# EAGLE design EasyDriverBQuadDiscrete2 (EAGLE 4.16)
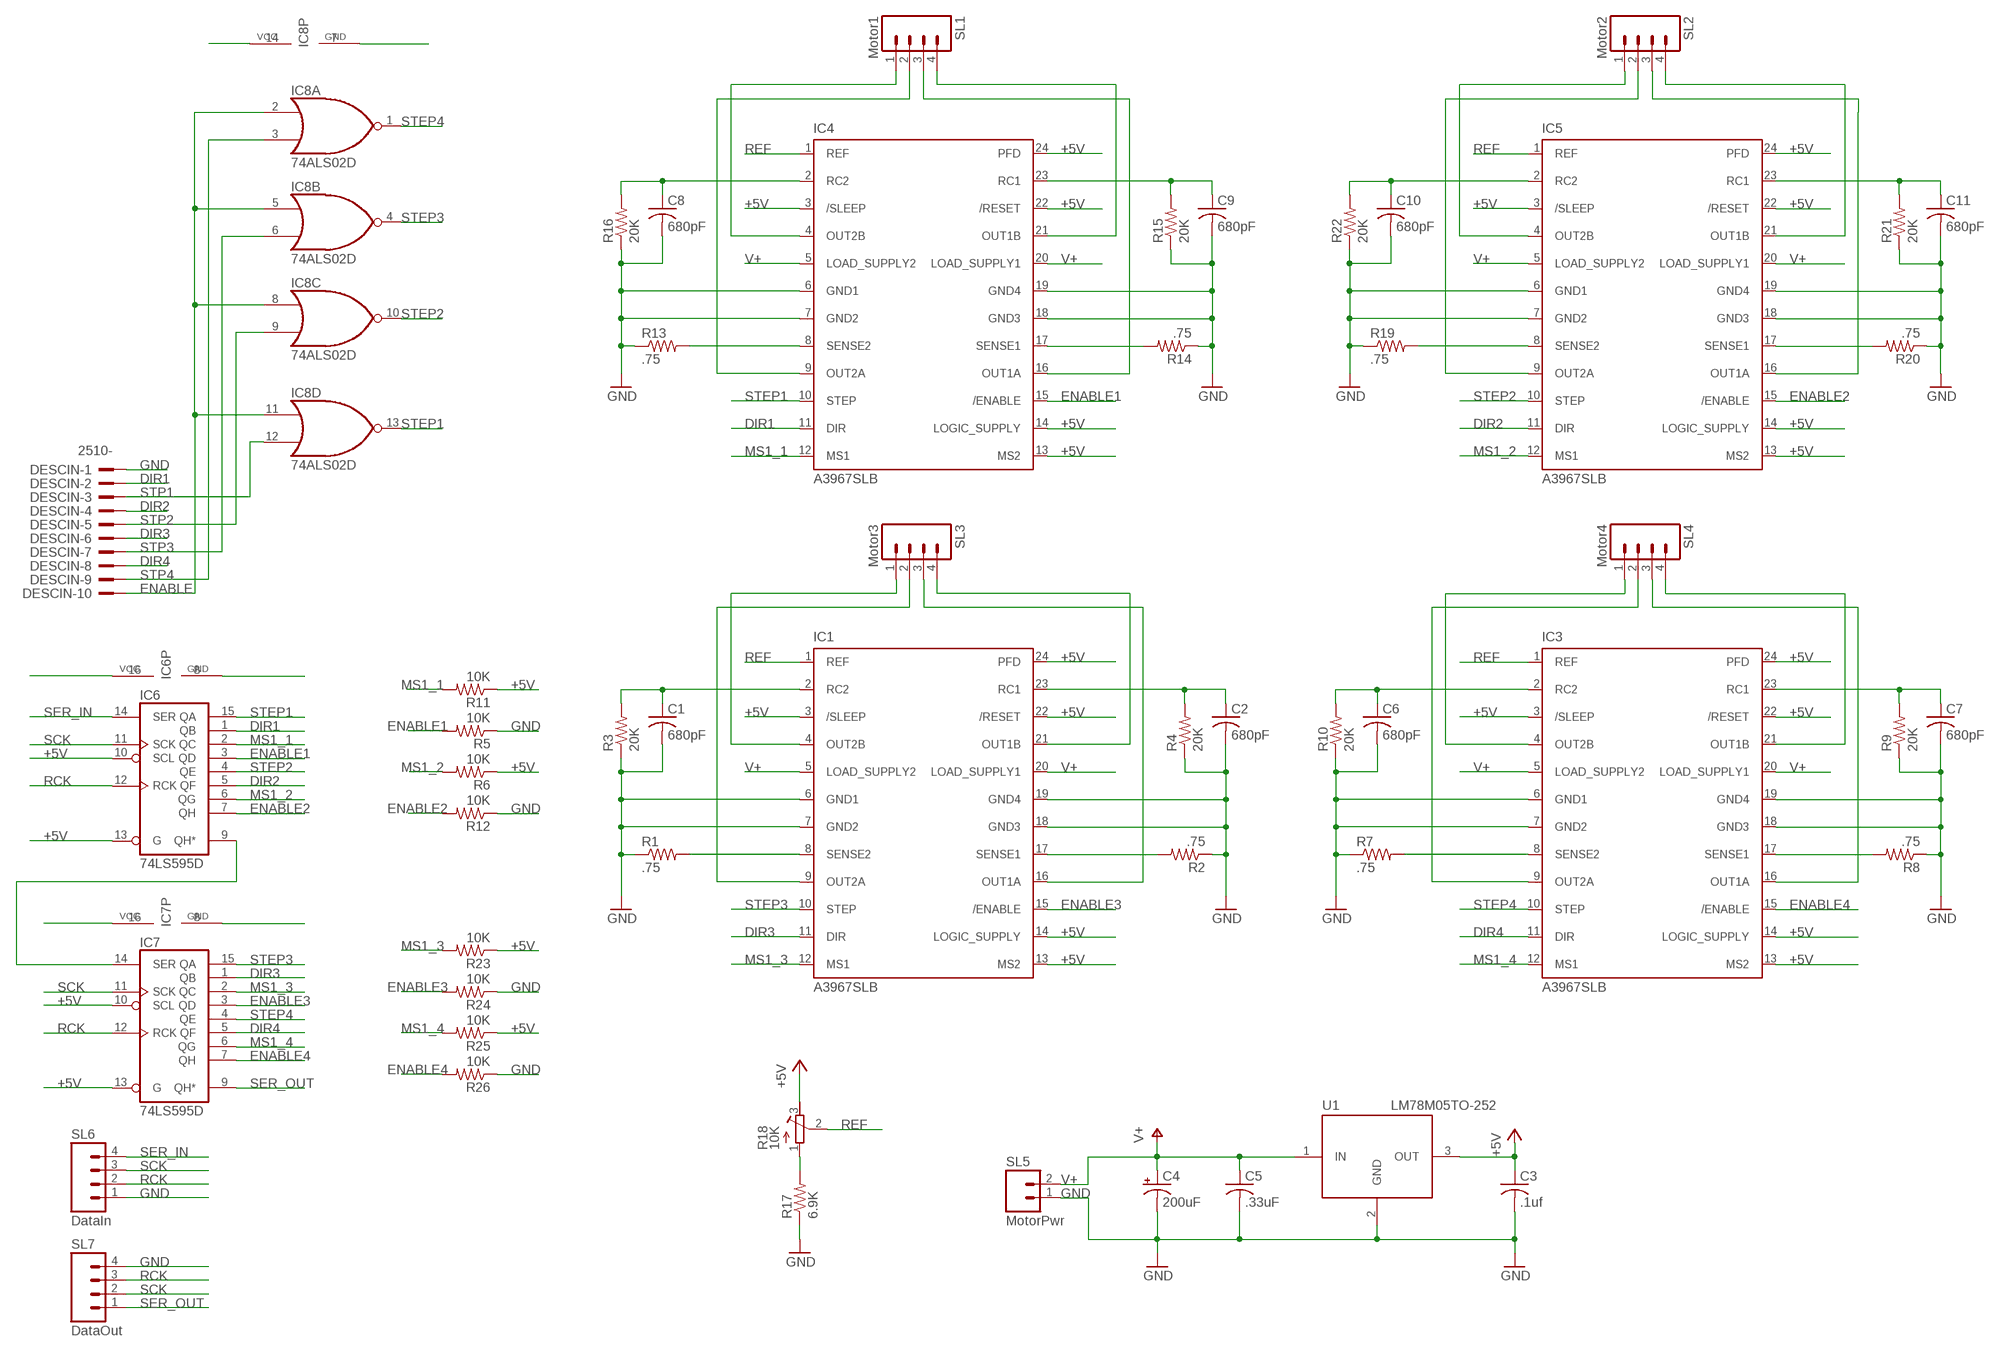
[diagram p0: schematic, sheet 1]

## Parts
C1  680pF  C-USC0603  [C0603]
C2  680pF  C-USC0603  [C0603]
C3  .1uf  C-USC0603  [C0603]
C4  200uF  CPOL-USG  [PANASONIC_G]
C5  .33uF  C-USC0603  [C0603]
C6  680pF  C-USC0603  [C0603]
C7  680pF  C-USC0603  [C0603]
C8  680pF  C-USC0603  [C0603]
C9  680pF  C-USC0603  [C0603]
C10  680pF  C-USC0603  [C0603]
C11  680pF  C-USC0603  [C0603]
DESCIN  2510-  [PAK100/2500-10]
IC1  A3967SLB  [SO24W]
IC3  A3967SLB  [SO24W]
IC4  A3967SLB  [SO24W]
IC5  A3967SLB  [SO24W]
IC6  74LS595D  [SO16]
IC7  74LS595D  [SO16]
IC8  74ALS02D  [SO14]
R1  .75  R-US_R0805  [R0805]
R2  .75  R-US_R0805  [R0805]
R3  20K  R-US_R0603  [R0603]
R4  20K  R-US_R0603  [R0603]
R5  10K  R-US_R0603  [R0603]
R6  10K  R-US_R0603  [R0603]
R7  .75  R-US_R0805  [R0805]
R8  .75  R-US_R0805  [R0805]
R9  20K  R-US_R0603  [R0603]
R10  20K  R-US_R0603  [R0603]
R11  10K  R-US_R0603  [R0603]
R12  10K  R-US_R0603  [R0603]
R13  .75  R-US_R0805  [R0805]
R14  .75  R-US_R0805  [R0805]
R15  20K  R-US_R0603  [R0603]
R16  20K  R-US_R0603  [R0603]
R17  6.9K  R-US_R0603  [R0603]
R18  10K  R-TRIMM3103  [RTRIM3103]
R19  .75  R-US_R0805  [R0805]
R20  .75  R-US_R0805  [R0805]
R21  20K  R-US_R0603  [R0603]
R22  20K  R-US_R0603  [R0603]
R23  10K  R-US_R0603  [R0603]
R24  10K  R-US_R0603  [R0603]
R25  10K  R-US_R0603  [R0603]
R26  10K  R-US_R0603  [R0603]
SL1  Motor1  M04POLAR  [MOLEX-1X4]
SL2  Motor2  M04POLAR  [MOLEX-1X4]
SL3  Motor3  M04POLAR  [MOLEX-1X4]
SL4  Motor4  M04POLAR  [MOLEX-1X4]
SL5  MotorPwr  M02SCREW  [SCREWTERMINAL-3.5MM-2]
SL6  DataIn  M04POLAR  [MOLEX-1X4]
SL7  DataOut  M04POLAR  [MOLEX-1X4]
U1  LM78M05TO-252  [TOO-252]

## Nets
+5V: C3.1 IC1.3(/SLEEP) IC1.13(MS2) IC1.14(LOGIC_SUPPLY) IC1.22(/RESET) IC1.24(PFD) IC3.3(/SLEEP) IC3.13(MS2) IC3.14(LOGIC_SUPPLY) IC3.22(/RESET) IC3.24(PFD) IC4.3(/SLEEP) IC4.13(MS2) IC4.14(LOGIC_SUPPLY) IC4.22(/RESET) IC4.24(PFD) IC5.3(/SLEEP) IC5.13(MS2) IC5.14(LOGIC_SUPPLY) IC5.22(/RESET) IC5.24(PFD) IC6.10(SCL) IC6.13(G) IC6.16(VCC) IC7.10(SCL) IC7.13(G) IC7.16(VCC) IC8.14(P:VCC) R6.1 R11.1 R18.3(A) R23.1 R25.1 U1.3(OUT)
DIR1: DESCIN.2 IC4.11(DIR) IC6.1(QB)
DIR2: DESCIN.4 IC5.11(DIR) IC6.5(QF)
DIR3: DESCIN.6 IC1.11(DIR) IC7.1(QB)
DIR4: DESCIN.8 IC3.11(DIR) IC7.5(QF)
ENABLE: DESCIN.10 IC8.2(A:I0) IC8.5(B:I0) IC8.8(C:I0) IC8.11(D:I0)
ENABLE1: IC4.15(/ENABLE) IC6.3(QD) R5.2
ENABLE2: IC5.15(/ENABLE) IC6.7(QH) R12.2
ENABLE3: IC1.15(/ENABLE) IC7.3(QD) R24.2
ENABLE4: IC3.15(/ENABLE) IC7.7(QH) R26.2
GND: C1.2 C2.2 C3.2 C4.- C5.2 C6.2 C7.2 C8.2 C9.2 C10.2 C11.2 DESCIN.1 IC1.6(GND1) IC1.7(GND2) IC1.18(GND3) IC1.19(GND4) IC3.6(GND1) IC3.7(GND2) IC3.18(GND3) IC3.19(GND4) IC4.6(GND1) IC4.7(GND2) IC4.18(GND3) IC4.19(GND4) IC5.6(GND1) IC5.7(GND2) IC5.18(GND3) IC5.19(GND4) IC6.8(GND) IC7.8(GND) IC8.7(P:GND) R1.1 R2.1 R3.1 R4.1 R5.1 R7.1 R8.1 R9.1 R10.1 R12.1 R13.1 R14.1 R15.1 R16.1 R17.1 R19.1 R20.1 R21.1 R22.1 R24.1 R26.1 SL5.1 SL6.1 SL7.4 U1.2(GND)
MS1_1: IC4.12(MS1) IC6.2(QC) R11.2
MS1_2: IC5.12(MS1) IC6.6(QG) R6.2
MS1_3: IC1.12(MS1) IC7.2(QC) R23.2
MS1_4: IC3.12(MS1) IC7.6(QG) R25.2
N$1: IC1.8(SENSE2) R1.2
N$2: IC1.21(OUT1B) SL3.4
N$3: IC1.17(SENSE1) R2.2
N$4: IC4.4(OUT2B) SL1.1
N$5: C1.1 IC1.2(RC2) R3.2
N$6: IC5.4(OUT2B) SL2.1
N$7: C2.1 IC1.23(RC1) R4.2
N$9: IC1.9(OUT2A) SL3.2
N$11: IC3.16(OUT1A) SL4.3
N$12: IC3.21(OUT1B) SL4.4
N$13: IC3.4(OUT2B) SL4.1
N$14: IC3.9(OUT2A) SL4.2
N$15: IC1.4(OUT2B) SL3.1
N$16: IC4.16(OUT1A) SL1.3
N$17: IC5.16(OUT1A) SL2.3
N$19: IC3.8(SENSE2) R7.2
N$20: IC3.17(SENSE1) R8.2
N$21: C6.1 IC3.2(RC2) R10.2
N$22: C7.1 IC3.23(RC1) R9.2
N$23: IC1.16(OUT1A) SL3.3
N$26: IC4.9(OUT2A) SL1.2
N$28: IC4.21(OUT1B) SL1.4
N$31: IC4.8(SENSE2) R13.2
N$32: IC4.17(SENSE1) R14.2
N$33: C8.1 IC4.2(RC2) R16.2
N$34: C9.1 IC4.23(RC1) R15.2
N$35: R17.2 R18.1(E)
N$38: IC5.9(OUT2A) SL2.2
N$40: IC5.21(OUT1B) SL2.4
N$43: IC5.8(SENSE2) R19.2
N$44: IC5.17(SENSE1) R20.2
N$45: C10.1 IC5.2(RC2) R22.2
N$46: C11.1 IC5.23(RC1) R21.2
N$54: IC6.9(QH*) IC7.14(SER)
RCK: IC6.12(RCK) IC7.12(RCK) SL6.2 SL7.3
REF: IC1.1(REF) IC3.1(REF) IC4.1(REF) IC5.1(REF) R18.2(S)
SCK: IC6.11(SCK) IC7.11(SCK) SL6.3 SL7.2
SER_IN: IC6.14(SER) SL6.4
SER_OUT: IC7.9(QH*) SL7.1
STEP1: IC4.10(STEP) IC6.15(QA) IC8.13(D:O)
STEP2: IC5.10(STEP) IC6.4(QE) IC8.10(C:O)
STEP3: IC1.10(STEP) IC7.15(QA) IC8.4(B:O)
STEP4: IC3.10(STEP) IC7.4(QE) IC8.1(A:O)
STP1: DESCIN.3 IC8.12(D:I1)
STP2: DESCIN.5 IC8.9(C:I1)
STP3: DESCIN.7 IC8.6(B:I1)
STP4: DESCIN.9 IC8.3(A:I1)
V+: C4.+ C5.1 IC1.5(LOAD_SUPPLY2) IC1.20(LOAD_SUPPLY1) IC3.5(LOAD_SUPPLY2) IC3.20(LOAD_SUPPLY1) IC4.5(LOAD_SUPPLY2) IC4.20(LOAD_SUPPLY1) IC5.5(LOAD_SUPPLY2) IC5.20(LOAD_SUPPLY1) SL5.2 U1.1(IN)

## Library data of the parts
C1-C3 C5-C11 = rcl:C-US: CAPACITOR, American symbol
C4 = rcl:CPOL-US: POLARIZED CAPACITOR, American symbol
DESCIN = con-3m:2510-: 3M (TM) Pak 100 4-Wall Header Source: 3M
IC1 IC3-IC5 = Allegro:A3967SLB: ANALOG DEVICES
IC6 IC7 = SparkFunEagle-6-6-07:74*595: 8-bit SHIFT REGISTER, output latch
IC8 = 74xx-us:74*02: Quad 2-input NOR gate
R1-R17 R19-R26 = rcl:R-US_: RESISTOR, American symbol
R18 = rcl:R-TRIMM: Trimm resistor
SL1-SL4 SL6 SL7 = SparkFunEagle-6-6-07:M04: Header 4 Standard 4-pin 0.1" header. Use with straight break away headers (SKU : PRT-00116), right angle break away headers (PRT-00553), swiss pins (PRT-00743), machine pins (PRT-00117), and female headers (PRT-00115). Molex polarized connector foot print use with SKU : PRT-08231 with associated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
SL5 = SparkFunEagle-6-6-07:M02: Header 2
U1 = BriansLibrary:LM78M05

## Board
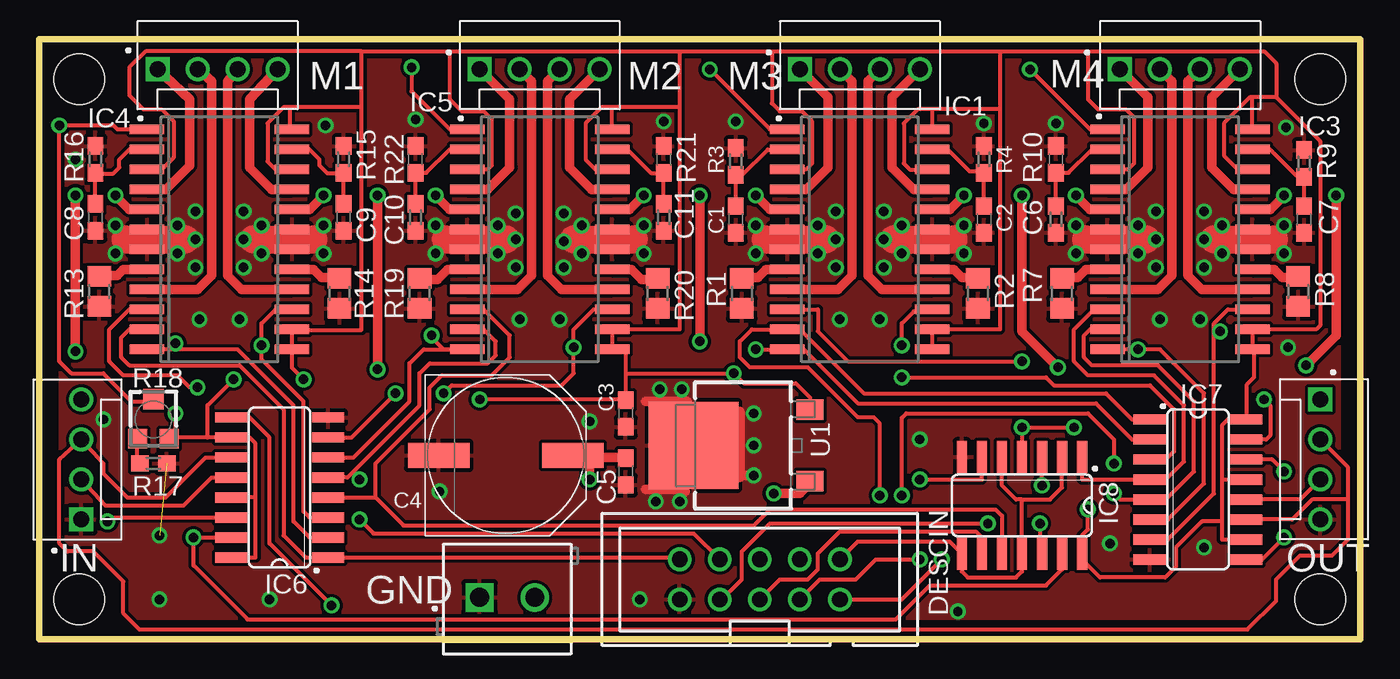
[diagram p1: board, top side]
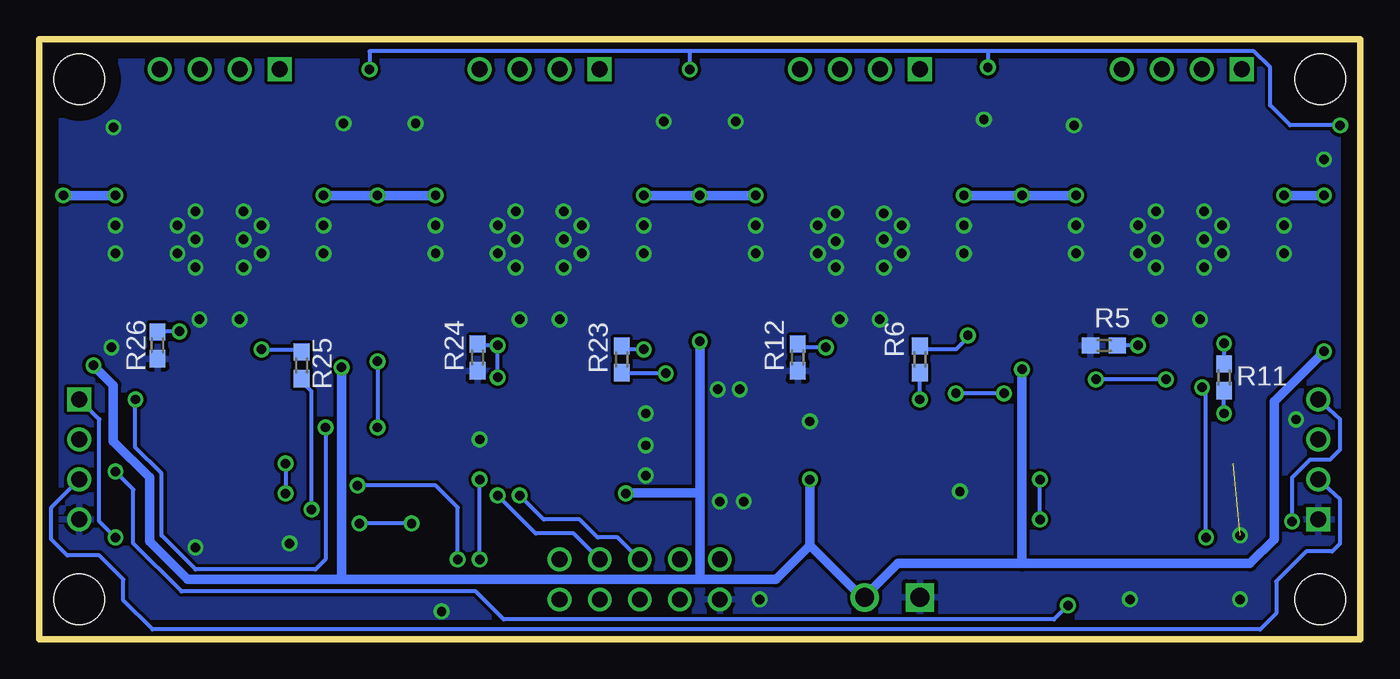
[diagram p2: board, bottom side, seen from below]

Size 83.82 x 38.1 mm. Coordinates in mm from the lower left corner, seen from the top.
Outline: 0,38.1 0,0 83.82,0 83.82,38.1 0,38.1
Copper layers (1*16): Top 0.035mm / dielectric 1.5mm / Bottom 0.035mm
Design rules "default": minimum track width 8mil, minimum drill 20mil, track to track 8mil, track to pad 8mil, pad to pad 8mil, via to via 8mil, smd to smd 8mil, copper to edge 40mil, drill to drill 8mil, minimum pad ring 10mil, minimum via ring 8mil, stop-mask expansion 4mil, vias tented up to drill 0mil, thermal gap 10mil
Holes 3.2 mm at 2.54,35.56 81.28,35.56 2.54,2.54 81.28,2.54

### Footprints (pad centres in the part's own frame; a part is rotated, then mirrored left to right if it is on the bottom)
C0603 = smd 1.1 x 1: 1 -0.85,0; 2 0.85,0
PANASONIC_G = smd 3.9 x 1.6: + 4.25,0; - -4.25,0
PAK100/2500-10 = drill 1 pad 1.422 round: 1 -5.08,-1.27; 2 -5.08,1.27; 3 -2.54,-1.27; 4 -2.54,1.27; 5 0,-1.27; 6 0,1.27; 7 2.54,-1.27; 8 2.54,1.27; 9 5.08,-1.27; 10 5.08,1.27
SO24W = smd 0.6 x 2.2: 1 -6.985,-4.6; 2 -5.715,-4.6; 3 -4.445,-4.6; 4 -3.175,-4.6; 5 -1.905,-4.6; 6 -0.635,-4.6; 7 0.635,-4.6; 8 1.905,-4.6; 9 3.175,-4.6; 10 4.445,-4.6; 11 5.715,-4.6; 12 6.985,-4.6; 13 6.985,4.6; 14 5.715,4.6; 15 4.445,4.6; 16 3.175,4.6; 17 1.905,4.6; 18 0.635,4.6; 19 -0.635,4.6; 20 -1.905,4.6; 21 -3.175,4.6; 22 -4.445,4.6; 23 -5.715,4.6; 24 -6.985,4.6
SO16 = smd 0.66 x 2.032: 1 -4.445,-3.073; 2 -3.175,-3.073; 3 -1.905,-3.073; 4 -0.635,-3.073; 5 0.635,-3.073; 6 1.905,-3.073; 7 3.175,-3.073; 8 4.445,-3.073; 9 4.445,3.073; 10 3.175,3.073; 11 1.905,3.073; 12 0.635,3.073; 13 -0.635,3.073; 14 -1.905,3.073; 15 -3.175,3.073; 16 -4.445,3.073
SO14 = smd 0.66 x 2.032: 1 -3.81,-3.073; 2 -2.54,-3.073; 3 -1.27,-3.073; 4 0,-3.073; 5 1.27,-3.073; 6 2.54,-3.073; 7 3.81,-3.073; 8 3.81,3.073; 9 2.54,3.073; 10 1.27,3.073; 11 0,3.073; 12 -1.27,3.073; 13 -2.54,3.073; 14 -3.81,3.073
R0805 = smd 1.3 x 1.5: 1 -0.95,0; 2 0.95,0
R0603 = smd 1.1 x 1: 1 -0.85,0; 2 0.85,0
RTRIM3103 = smd 1.2 x 1.25: 1 -1,-1.225; 3 1,-1.225 | smd 1.3 x 1.3: 2 0,1.3
MOLEX-1X4 = drill 1.016 square: 1 3.81,-2.54 | drill 1.016 round: 2 1.27,-2.54; 3 -1.27,-2.54; 4 -3.81,-2.54
SCREWTERMINAL-3.5MM-2 = drill 1.2 square: 1 -1.905,0 | drill 1.2 round: 2 1.595,0
TOO-252 = smd 1.3 x 1.7: 1 -2.28,-3.7; 3 2.28,-3.7 | smd 5.5 x 5.7: 2 0,3.7

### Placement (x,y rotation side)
C1  44.2,26.67 270 top
C2  59.94,26.67 270 top
C3  37.21,14.35 270 top
C4  29.59,11.68 0 top
C5  37.21,10.67 270 top
C6  64.52,30.48 90 top
C7  80.26,26.67 270 top
C8  3.56,26.8 270 top
C9  19.3,26.8 270 top
C10  23.88,30.48 90 top
C11  39.62,30.48 90 top
DESCIN  45.72,3.81 0 top
IC1  52.07,25.4 270 top
IC3  72.39,25.4 270 top
IC4  11.43,25.4 270 top
IC5  31.75,25.4 270 top
IC6  15.24,9.65 90 top
IC7  73.53,9.53 270 top
IC8  62.36,8.51 180 top
R1  44.58,21.97 90 top
R2  59.56,21.97 90 top
R3  44.2,30.35 270 top
R4  59.94,30.48 270 top
R5  16.26,18.67 0 bottom
R6  27.94,17.78 90 bottom
R7  64.9,21.97 90 top
R8  79.88,22.1 90 top
R9  80.26,30.23 270 top
R10  64.52,26.67 90 top
R11  8.64,16.64 90 bottom
R12  35.69,17.91 90 bottom
R13  3.81,22.1 90 top
R14  19.05,21.97 90 top
R15  19.3,30.48 270 top
R16  3.56,30.48 270 top
R17  7.24,11.18 180 top
R18  7.24,13.97 0 top
R19  24.13,21.97 90 top
R20  39.24,21.97 90 top
R21  39.62,26.8 90 top
R22  23.88,26.8 90 top
R23  46.86,17.78 90 bottom
R24  56.01,17.91 90 bottom
R25  67.18,17.4 90 bottom
R26  76.33,18.67 90 bottom
SL1  11.3,33.66 180 top
SL2  31.75,33.66 180 top
SL3  52.07,33.66 180 top
SL4  72.39,33.66 180 top
SL5  29.84,2.67 0 top
SL6  5.21,11.43 270 top
SL7  78.74,11.43 90 top
U1  45.21,12.32 90 top

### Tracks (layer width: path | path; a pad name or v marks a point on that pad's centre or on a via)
+5V  (via drill 0.6)
  Top 0.254: 16.89,32.38 IC4.24 15.88,32.38 15.88,33.78 | 16,19.68 15.88,19.56 | 12.19,12.83 13.34,12.83 13.72,12.45 13.72,9.02 | 13.72,9.02 IC6.13 | IC6.16 13.72,5.21 13.72,9.02 | 77.09,19.68 77.12,19.71 77.12,19.66 | 56.67,19.59 56.64,19.56 | IC4.22 14.99,29.84 14.48,30.35 14.48,32.77 15.49,33.78 15.88,33.78 | 5.97,29.84 IC4.3 7.75,29.84 8.51,30.61 8.51,32.89 7.75,33.66 6.6,33.66 5.71,34.54 5.71,36.32 6.73,37.34 20.45,37.34 | IC5.22 35.31,29.84 34.67,30.48 34.67,32.77 35.69,33.78 36.32,33.78 | 40.64,33.78 36.32,33.78 | 40.64,37.34 40.64,33.78 | 40.64,33.78 40.64,19.68 IC5.14 36.35,18.44 36.32,18.41 IC5.13 37.21,18.41 37.21,16.89 | IC5.3 28.45,29.84 28.7,30.1 28.7,33.02 28.19,33.53 26.8,33.53 26.04,34.29 26.04,37.34 | IC1.3 48.64,29.84 49.02,30.23 49.02,32.89 48.39,33.53 46.99,33.53 46.48,34.04 46.48,37.34 | IC1.22 55.24,29.84 54.86,30.23 54.86,32.77 55.75,33.66 56.64,33.66 | 60.96,33.66 56.64,33.66 | IC3.3 69.09,29.84 69.47,30.23 69.47,33.15 68.96,33.66 67.18,33.66 66.55,34.29 66.55,37.34 | IC3.22 76.07,29.84 75.18,30.73 75.18,32.77 76.83,34.42 76.96,34.42 | 78.49,34.42 81.28,31.62 81.28,19.94 81.03,19.68 77.09,19.68 | 78.49,34.42 76.96,34.42 | 20.45,33.78 15.88,33.78 | IC5.24 36.32,32.38 36.32,33.78 | 16,19.68 IC4.14 | 16.03,19.66 IC4.13 16.03,17.24 v16.76,16.51 | 16.03,19.66 16,19.68 | IC1.24 56.67,32.36 56.64,32.38 56.64,33.66 | 40.64,37.34 46.48,37.34 | 56.64,19.68 56.64,18.41 IC1.13 | IC3.13 77.09,18.41 | IC3.13 76.99,19.66 76.96,19.68 IC3.14 77.09,19.68 | 76.96,34.42 76.96,32.38 IC3.24 | 20.45,37.34 26.04,37.34 | IC7.10 75.06,6.35 75.06,7.49 | 75.06,10.16 75.06,7.49 | 75.06,10.16 IC7.13
  Top 0.254: 75.06,10.16 75.06,13.59 75.44,13.97 IC7.16 76.61,16.15 77.09,16.64 77.09,18.29 76.96,18.41 IC3.13 | 75.06,7.49 73.79,7.49 72.14,5.84 72.14,4.62 71.45,3.94 67.31,3.94 66.17,5.08 IC8.14 66.17,6.6 66.55,6.99 v66.55,8.26 | 20.45,33.78 20.45,37.34 | 26.04,37.34 40.64,37.34 | 46.48,37.34 60.96,37.34 | 60.96,37.34 66.55,37.34 | 66.55,37.34 77.72,37.34 78.49,36.58 78.49,34.42 | 60.96,37.34 60.96,33.66 | 60.96,33.66 60.96,19.68 56.64,19.68 | 56.64,19.68 IC1.14 | 10.67,12.83 8.26,12.83 8.26,12.76 R18.3 8.24,12.81 8.64,13.21 v8.64,14.35 | 12.19,12.83 IC6.10 | 12.19,12.83 10.67,12.83 | 37.21,15.24 v27.94,15.24 | 16.03,19.66 20.45,19.66 20.45,33.78 | v12.32,16.51 10.67,14.86 10.67,12.83 | 37.21,15.24 C3.1 | 37.21,16.89 v44.07,16.89 44.7,16.26 48.01,16.26 48.91,15.35 48.91,14.62 48.9,14.61 U1.3 | 37.21,16.89 37.21,15.24
  Top 0.406: IC5.14 36.32,19.68 | IC1.14 56.67,19.59
  Bottom 0.254: v27.94,15.24 R6.1 | v8.64,14.35 R11.1 | R23.1 46.86,16.89 v44.07,16.89 | R25.1 67.18,16.38 66.55,15.75 v66.55,8.26 | v12.32,16.51 v16.76,16.51
DIR1
  Top 0.254: 7.75,19.68 IC4.11 5.71,19.68 5.21,19.18 5.21,17.91 5.71,17.4 12.7,17.4 15.49,14.61 15.49,6.6 16.89,5.21 IC6.1 40.51,5.21 DESCIN.2
DIR2  (via drill 0.6)
  Top 0.254: 27.18,19.68 IC5.11 28.19,19.68 28.96,18.92 28.96,18.03 28.45,17.53 24.77,17.53 24.13,16.89 24.13,14.86 19.94,10.67 | IC6.5 19.56,10.29 19.94,10.67 | DESCIN.4 41.53,6.73 21.21,6.73 v20.32,7.62 | v20.32,10.16 20.32,10.29 19.94,10.67
  Bottom 0.254: v20.32,7.62 v20.32,10.16
DIR3  (via drill 0.6)
  Top 0.254: IC7.1 69.34,13.97 67.69,15.62 52.32,15.62 48.26,19.68 IC1.11 45.21,19.68 44.45,18.92 44.45,17.91 45.09,17.27 48.77,17.27 51.94,14.1 52.96,14.1 53.34,13.72 v53.34,9.14
  Bottom 0.254: v53.34,9.14 51.82,7.62 49.53,7.62 48.39,6.48 47.12,6.48 DESCIN.6
DIR4  (via drill 0.6)
  Top 0.254: IC3.11 66.67,19.68 66.29,19.3 66.29,17.91 66.8,17.4 70.99,17.4 73.28,15.11 73.28,10.67 71.5,8.89 IC7.5 68.58,8.89 v68.2,9.27 | v68.2,11.18 68.2,12.7 66.55,14.35 55.02,14.35 54.74,14.07 v54.74,9.14
  Bottom 0.254: v68.2,11.18 v68.2,9.27 | DESCIN.8 49.91,6.73 52.32,6.73 v54.74,9.14
ENABLE
  Top 0.254: IC8.2 64.9,9.65 64.14,8.89 62.36,8.89 | 62.36,8.89 61.98,8.89 61.09,9.78 IC8.5 | IC8.11 62.36,6.1 | IC8.11 62.36,8.89 | IC8.11 62.36,4.32 61.98,3.94 58.93,3.94 58.55,4.32 IC8.8 57.76,6.22 51.94,6.22 DESCIN.10
ENABLE1  (via drill 0.6)
  Top 0.254: IC4.15 14.99,20.95 14.1,20.07 14.1,19.05 | 14.1,19.05 14.1,18.92 | IC6.3 17.14,7.75 16.76,8.13 16.76,15.11 14.1,17.78 v14.1,18.67 14.1,19.05
  Bottom 0.254: v14.1,18.67 R5.2
ENABLE2  (via drill 0.6)
  Top 0.254: IC5.15 36.32,20.95 36.2,20.83 36.07,20.95 35.18,20.95 33.91,19.68 v33.91,18.54 33.91,16.89 33.15,16.13 26.16,16.13 v25.65,15.62 | IC6.7 19.81,12.83 v22.61,15.62
  Bottom 0.254: v33.91,18.54 35.69,18.54 R12.2 | v22.61,15.62 v25.65,15.62
ENABLE3  (via drill 0.6)
  Top 0.254: 56.64,20.83 56.67,20.86 IC1.15 | 56.64,20.83 57.4,20.83 | 56.64,20.83 55.5,20.83 54.74,20.07 v54.74,18.67 | IC7.3 71.5,11.43 72.01,11.94 72.01,14.61 70.48,16.13 64.39,16.13 63.88,16.64 v54.74,16.64
  Bottom 0.254: R24.2 56.01,18.67 v54.74,18.67 v54.74,16.64
ENABLE4  (via drill 0.6)
  Top 0.254: IC7.7 71.63,6.35 74.55,9.27 74.55,19.56 | IC3.15 75.44,20.95 74.55,20.07 74.55,19.56 | 74.55,19.56 v74.93,19.56
  Bottom 0.254: R26.2 76.33,19.56 v74.93,19.56
GND  (via drill 0.6)  (1 unrouted)
  Top 0.254: 6.86,26.04 6.77,25.95 | IC4.19 16.13,26.04 | IC6.8 17.91,14.1
  Top 0.406: IC4.6 6.86,26.04 | IC4.7 6.86,24.77 | IC4.18 16,24.77
  Top 0.61: 16.13,26.04 16.22,25.95 | 38.48,15.11 41.02,15.11 | 41.02,15.11 41.15,15.11 | 38.48,9.53 40.89,9.53 41.02,9.4 40.64,9.02 v40.64,8.76 | 44.45,14.48 44.45,10.29 44.58,10.41 v45.34,10.41 | v40.77,15.88 40.77,15.37 41.02,15.11
  Top 1.778: 13.59,25.4 17.4,25.4 | 5.46,25.4 9.27,25.4 | 33.91,25.4 37.72,25.4 | 25.78,25.4 29.59,25.4 | 46.1,25.4 49.91,25.4 | 54.23,25.4 58.04,25.4 | 74.55,25.4 78.36,25.4 | 66.42,25.4 70.23,25.4
  other vias: 8.76,26.29 8.76,24.51 14.1,24.51 14.1,26.29 2.29,30.48 18.16,32.64 23.88,33.02 18.03,24.51 4.83,26.29 4.83,24.51 9.91,27.18 9.91,23.62 18.03,26.29 12.95,27.18 12.95,23.62 9.91,25.4 12.95,25.4 38.35,26.29 38.35,24.51 34.42,26.29 34.42,24.51 33.27,25.27 33.27,27.05 33.27,23.62 30.23,27.05 29.08,26.29 30.23,25.4 29.08,24.51 30.23,23.62 25.15,26.29 25.15,24.51 58.67,26.29 58.67,24.51 54.74,26.29 54.74,24.51 53.59,25.4 53.59,27.18 53.59,23.62 50.55,25.4 50.55,27.18 50.55,23.62 49.4,26.29 49.4,24.51 45.47,26.29 45.47,24.51 78.99,24.51 78.99,26.29 75.06,26.29 75.06,24.51 73.91,25.4 73.91,27.18 73.91,23.62 70.87,27.18 70.87,25.4 70.87,23.62 69.72,24.51 69.72,26.29 65.79,26.29 65.79,24.51 44.2,32.89 64.52,32.77 39.62,32.89 59.94,32.77 79.12,32.51 73.66,20.32 71.12,20.32 53.34,20.32 50.8,20.32 33.02,20.32 30.48,20.32 12.7,20.32 10.16,20.32 38.1,2.54 4.06,13.97 34.92,13.84 7.62,2.54 73.91,5.84 58.29,1.78 25.4,9.4 14.61,2.54 7.62,6.6 55.88,12.7 67.94,6.1 79.25,18.54 45.34,14.35 45.34,12.32 39.12,8.76 39.37,15.88
  pour Bottom: 0,38.1 0,0 83.82,0 83.82,38.1
  pour Top: 0,38.1 0,0 83.82,0 83.82,38.1
MS1_1  (via drill 0.6)
  Top 0.254: IC6.2 17.14,6.48 16.13,7.49 16.13,14.86 12.57,18.41 8.64,18.41 | 8.64,18.41 IC4.12 | 8.64,18.41 v8.64,18.8
  Bottom 0.254: v8.64,18.8 R11.2
MS1_2  (via drill 0.6)
  Top 0.254: v24.89,19.3 24.89,19.18 25.65,18.41 IC5.12 24.38,18.41 23.5,17.53 23.5,15.11 19.94,11.56 IC6.6
  Bottom 0.254: R6.2 27.94,18.54 28.07,18.41 25.65,18.41 24.89,19.18 v24.89,19.3
MS1_3  (via drill 0.6)
  Top 0.254: IC7.2 69.34,12.7 67.06,14.99 51.94,14.99 48.51,18.41 47.5,18.41 | 47.5,18.41 47.62,18.54 | 47.5,18.41 IC1.12 v45.47,18.41
  Bottom 0.254: R23.2 46.86,18.67 46.61,18.41 v45.47,18.41
MS1_4  (via drill 0.6)
  Top 0.254: 70.46,7.64 70.36,7.75 | IC7.6 70.46,7.64 | 70.46,7.64 70.48,7.62 71.63,7.62 73.91,9.91 73.91,15.62 71.12,18.41 v69.72,18.41 IC3.12
  Bottom 0.254: R25.2 67.18,18.29 67.31,18.41 v69.72,18.41
N$1
  Top 0.61: IC1.8 46.1,23.5 45.59,22.99 44.58,22.99 R1.2
N$2
  Top 0.61: SL3.4 54.1,34.42 54.1,29.97 55.5,28.57 IC1.21
N$3
  Top 0.61: IC1.17 58.04,23.5 58.55,22.99 59.56,22.99 R2.2
N$4
  Top 0.61: IC4.4 8,28.57 9.53,30.1 9.53,34.29 SL1.1
N$5
  Top 0.254: C1.1 R3.2 44.62,29.5 46.23,31.11 47.37,31.11
  Top 0.406: 47.37,31.11 IC1.2
N$6
  Top 0.61: IC5.4 28.45,28.57 29.84,29.97 29.84,34.29 SL2.1
N$7
  Top 0.254: IC1.23 57.66,31.11 59.05,29.72 59.82,29.72 | C2.1 59.94,29.59 R4.2
  Top 0.406: 59.94,29.59 59.91,29.63 | 59.91,29.63 R4.2 | 59.91,29.63 59.82,29.72
N$9
  Top 0.406: IC1.9 47.37,22.23
  Top 0.61: SL3.2 51.56,35.43 51.56,23.11 50.67,22.23 IC1.9
N$11
  Top 0.61: IC3.16 73.79,22.23 72.9,23.11 72.9,35.43 SL4.3
N$12
  Top 0.61: IC3.21 75.82,28.57 74.42,29.97 74.42,34.42 SL4.4
N$13
  Top 0.61: IC3.4 68.96,28.57 70.36,29.97 70.36,34.42 SL4.1
N$14
  Top 0.61: IC3.9 70.99,22.23 71.88,23.11 71.88,35.43 SL4.2
N$15
  Top 0.61: IC1.4 48.64,28.57 50.04,29.97 50.04,34.42 SL3.1
N$16
  Top 0.61: IC4.16 12.83,22.23 11.94,23.11 11.94,35.43 SL1.3
N$17
  Top 0.61: IC5.16 33.15,22.23 32.26,23.11 32.26,35.43 SL2.3
N$19
  Top 0.406: 67.82,23.5 IC3.8
  Top 0.61: R7.2 64.9,22.99 65.91,22.99 66.42,23.5 67.82,23.5
N$20
  Top 0.61: R8.2 79.88,22.99 78.87,22.99 78.36,23.5 IC3.17
N$21
  Top 0.254: R10.2 64.52,29.59 | C6.1 65.32,29.63 66.8,31.11 IC3.2
  Top 0.406: 64.52,29.59 C6.1
N$22
  Top 0.254: IC3.23 78.11,31.11 79.76,29.46 80.14,29.46 80.26,29.34 R9.2 C7.1 80.26,27.43
N$23
  Top 0.61: IC1.16 53.47,22.23 52.58,23.11 52.58,35.43 SL3.3
N$26
  Top 0.61: IC4.9 10.03,22.23 10.92,23.11 10.92,35.43 SL1.2
N$28
  Top 0.61: IC4.21 14.73,28.57 13.34,29.97 13.34,34.29 SL1.4
N$31
  Top 0.61: 6.86,23.5 IC4.8 5.33,23.5 4.95,23.11 3.81,23.11 R13.2 3.81,22.99
N$32
  Top 0.61: IC4.17 17.4,23.5 17.91,22.99 18.92,22.99 | 18.92,22.99 19.05,22.99 | 18.92,22.99 18.92,22.86 18.98,22.92 R14.2
N$33
  Top 0.254: IC4.2 5.71,31.11 5.08,30.48 5.08,29.97 4.7,29.59 3.56,29.59 | C8.1 3.56,29.59 | 3.56,29.59 R16.2
  Top 0.406: IC4.2 6.86,31.11
N$34
  Top 0.254: IC4.23 17.14,31.11 17.78,30.48 17.78,30.1 18.29,29.59 19.3,29.59 | C9.1 19.3,29.59 | 19.3,29.59 R15.2
N$35
  Top 0.254: R17.2 6.22,11.18 6.22,12.7 6.35,12.7 6.35,12.74 R18.1
N$38
  Top 0.61: IC5.9 30.35,22.23 31.24,23.11 31.24,35.43 SL2.2
N$40
  Top 0.61: IC5.21 35.05,28.57 33.66,29.97 33.66,34.29 SL2.4
N$43
  Top 0.406: 24.26,22.86 24.2,22.92 R19.2
  Top 0.61: IC5.8 25.91,23.5 25.27,22.86 24.26,22.86
N$44
  Top 0.406: 39.24,22.99 R20.2
  Top 0.61: 39.24,22.99 39.12,22.86 38.23,22.86 37.59,23.5 IC5.17
N$45
  Top 0.254: R22.2 C10.1 24.55,29.63 26.04,31.11 IC5.2
N$46
  Top 0.254: IC5.23 37.34,31.11 38.86,29.59 39.62,29.59 R21.2
  Top 0.406: 39.62,29.59 C11.1
N$54  (via drill 0.6)
  Top 0.254: 76.58,11.43 IC7.14 78.23,11.43 v78.99,10.67 | IC6.9 13.34,14.1 14.61,12.83 14.61,6.1 v18.54,2.16
  Bottom 0.254: v18.54,2.16 19.43,1.27 54.36,1.27 56.13,3.05 74.8,3.05 77.85,6.1 77.85,9.53 v78.99,10.67
RCK
  Top 0.254: 12.19,10.29 IC6.12 10.92,10.29 9.14,8.51 4.19,8.51 SL6.2 | 76.58,8.89 IC7.12 80.01,8.89 SL7.3
  Bottom 0.254: SL6.2 1.27,8.89 1.27,6.1 1.78,5.59 3.43,5.59 5.33,3.68 5.33,1.65 6.35,0.64 76.64,0.64 78.49,2.48 78.49,3.81 80.01,5.33 82.04,5.33 83.06,6.35 83.06,8.38 SL7.3
REF  (via drill 0.6)
  Top 0.254: IC4.1 4.95,32.38 4.7,32.64 v1.27,32.64 1.27,17.65 2.03,16.89 4.06,16.89 5.84,15.11 7.24,15.11 R18.2 | v23.62,36.32 23.62,34.8 26.04,32.38 27.18,32.38 | IC1.1 47.37,32.38 | v42.55,36.2 46.35,32.38 IC1.1 | IC1.1 47.62,32.38 | v62.87,36.2 66.67,32.38 67.82,32.38
  Top 0.406: 27.18,32.38 IC5.1 | IC1.1 47.5,32.38 | 67.82,32.38 IC3.1
  Bottom 0.254: v1.27,32.64 4.45,32.64 5.71,33.91 5.71,36.32 6.73,37.34 23.62,37.34 | 23.62,37.34 v23.62,36.32 | 23.62,37.34 42.55,37.34 | 42.55,37.34 v42.55,36.2 | 42.55,37.34 62.87,37.34 v62.87,36.2
SCK
  Top 0.254: 12.19,11.56 IC6.11 10.54,11.56 8,9.02 5.59,9.02 4.06,10.54 4.06,11.18 SL6.3 1.27,11.43 1.27,6.1 1.78,5.59 3.43,5.59 5.33,3.68 5.33,1.65 6.35,0.64 76.67,0.64 78.49,2.45 78.49,3.81 80.01,5.33 82.04,5.33 83.06,6.35 83.06,8.89 | 83.06,8.89 83.06,10.92 SL7.2 | IC7.11 79.5,7.62 80.77,8.89 83.06,8.89
SER_IN  (via drill 0.6)
  Top 0.254: IC6.14 4.57,7.75 v4.32,7.49
  Bottom 0.254: v4.32,7.49 4.32,10.29 3.17,11.43 1.91,11.43 1.27,12.06 1.27,13.97 SL6.4
SER_OUT  (via drill 0.6)
  Top 0.254: 76.58,5.08 IC7.9 77.6,5.08 v78.99,6.48
  Bottom 0.254: v78.99,6.48 80.01,7.49 80.01,13.97 SL7.1
STEP1  (via drill 0.6)
  Top 0.254: IC4.10 5.71,20.95 4.45,19.68 4.45,17.65 5.33,16.76 8.76,16.76 9.53,16 v10.03,16 | IC6.15 v9.78,6.48 9.78,4.7 13.21,1.27 54.36,1.27 56.52,3.43 63.88,3.43 64.9,4.45 64.9,5.46 64.87,5.44 IC8.13
  Bottom 0.254: v9.78,6.48 9.78,16 v10.03,16
STEP2
  Top 0.254: 61.09,6.1 IC8.10 61.09,7.85 60.69,8.26 46.35,8.26 45.34,7.24 23.11,7.24 21.34,9.02 | IC5.10 28.19,20.95 29.84,19.3 29.84,17.91 28.7,16.76 25.53,16.76 24.77,16 24.77,14.61 21.34,11.18 21.34,9.02 | IC6.4 21.34,9.02
STEP3  (via drill 0.6)
  Top 0.254: v62.36,17.65 51.31,17.65 49.4,19.56 49.4,20.95 IC1.10 | IC8.4 v62.36,13.46 v65.66,13.46 | IC7.15 77.85,12.7 78.11,12.95 78.11,14.86 v77.72,15.24
  Bottom 0.254: v62.36,17.65 v62.36,13.46 | v77.72,15.24 77.72,12.19 76.07,10.54 76.07,6.6 73.91,4.45 66.29,4.45 65.66,5.08 v65.66,13.46
STEP4
  Top 0.254: IC8.1 66.17,10.16 70.36,10.16 | 67.82,20.95 IC3.10 66.93,20.95 65.66,19.68 65.66,17.65 66.55,16.76 70.74,16.76 72.64,14.86 72.64,11.3 71.5,10.16 70.36,10.16 | 70.36,10.16 IC7.4
STP1  (via drill 0.6)
  Top 0.254: v60.2,7.37 46.35,7.37 44.58,5.59 44.58,3.81 43.31,2.54 DESCIN.3 | IC8.12 63.63,6.1 63.5,6.22 v63.5,7.37
  Bottom 0.254: v60.2,7.37 v63.5,7.37
STP2
  Top 0.254: 59.82,6.1 IC8.9 59.82,6.48 59.44,6.86 50.8,6.86 49.4,5.46 49.4,4.45 48.77,3.81 46.99,3.81 DESCIN.5
STP3  (via drill 0.6)
  Top 0.254: IC8.6 59.82,10.16 v55.88,10.16 | DESCIN.7 49.53,3.81 51.82,3.81 53.09,5.08 v55.88,5.08
  Bottom 0.254: v55.88,5.08 v55.88,10.16
STP4  (via drill 0.6)
  Top 0.254: DESCIN.9 54.74,2.54 v57.28,5.08 | v63.63,9.78 IC8.3
  Bottom 0.254: v57.28,5.08 57.28,8.38 58.67,9.78 v63.63,9.78
V+  (via drill 0.6)
  Top 0.254: U1.1 48.9,10.03 48.9,9.91
  Top 0.61: 67.94,27.3 IC3.5 66.67,27.3 v65.79,28.19 | IC4.5 5.71,27.3 v4.83,28.19 | v18.03,28.19 17.14,27.3 IC4.20 | IC5.5 26.04,27.3 v25.15,28.19 | IC5.20 37.47,27.3 v38.35,28.19 | v45.47,28.19 46.35,27.3 IC1.5 | IC1.20 57.78,27.3 v58.67,28.19 | IC3.20 78.11,27.3 v78.99,28.19 | v80.39,17.4 82.3,19.3 v82.3,28.19 | v21.46,17.14 v21.46,28.19 | v41.91,18.92 v41.91,28.19 | v2.29,18.29 v2.29,28.19 | 34.92,11.56 33.78,11.56 33.84,11.62 C4.+ | v34.92,10.16 34.92,11.56 | C5.1 37.21,11.56 34.92,11.56 | v62.36,28.19 62.36,19.56 v64.64,17.27 | v46.61,9.27 48.26,9.27 48.9,9.91
  Bottom 0.61: v2.29,28.19 v4.83,28.19 | v18.03,28.19 v21.46,28.19 v25.15,28.19 | v38.35,28.19 v41.91,28.19 v45.47,28.19 | v58.67,28.19 v62.36,28.19 v65.79,28.19 | v82.3,28.19 v78.99,28.19 | 34.92,5.97 v34.92,10.16 | 41.91,3.81 41.91,9.31 | 41.91,9.31 v41.91,18.92 | 34.92,5.97 37.08,3.81 41.91,3.81 | 21.46,4.83 v21.46,17.14 | 21.46,4.83 29.34,4.83 31.5,2.67 | 41.91,3.81 64.64,3.81 | 64.64,3.81 74.42,3.81 76.83,6.22 76.83,10.29 79.12,12.57 79.12,16.13 v80.39,17.4 | 21.46,4.83 6.99,4.83 5.46,6.35 5.46,15.11 v2.29,18.29 | 31.5,2.67 31.62,2.67 34.92,5.97 | 31.5,2.67 SL5.2 | 64.64,3.81 v64.64,17.27 | 41.91,9.31 46.57,9.31 v46.61,9.27

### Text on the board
tPlace: M1 | M2 | M3 | M4 | IN | OUT | GND
_tsilk: M1 | M2 | M3 | M4 | IC5 | IC4 | IC1 | R16 | R15 | IC3 | R3 | R4 | R9 | R22 | R21 | R10 | C8 | C1 | C2 | C7 | C9 | C6 | C10 | C11 | R1 | R2 | R7 | R8 | R13 | R14 | R19 | R20 | R18 | IC7 | C3 | U1 | C5 | R17 | IC8 | C4 | DESCIN | IN | IC6 | 2 | OUT | GND | 1 | EDQ 0.8
_bsilk: EasyDriverQuad version 0.8 | 7.20.2007 | R5 | R6 | R12 | R23 | R24 | R26 | R11 | R25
